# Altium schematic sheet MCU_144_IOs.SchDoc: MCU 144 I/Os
size A3; Date: Not used; ApprovedBy: Not used; CheckedBy: Not used; Author: Not used; CompanyName: STMicroelectronics; DrawnBy: Not used; Engineer: Not used; Organization: Not used; Address1: Not used; Address2: Not used; Address3: Not used; Address4: Not used; DocumentNumber: 3; Revision: Not used; SheetNumber: 3; SheetTotal: 9
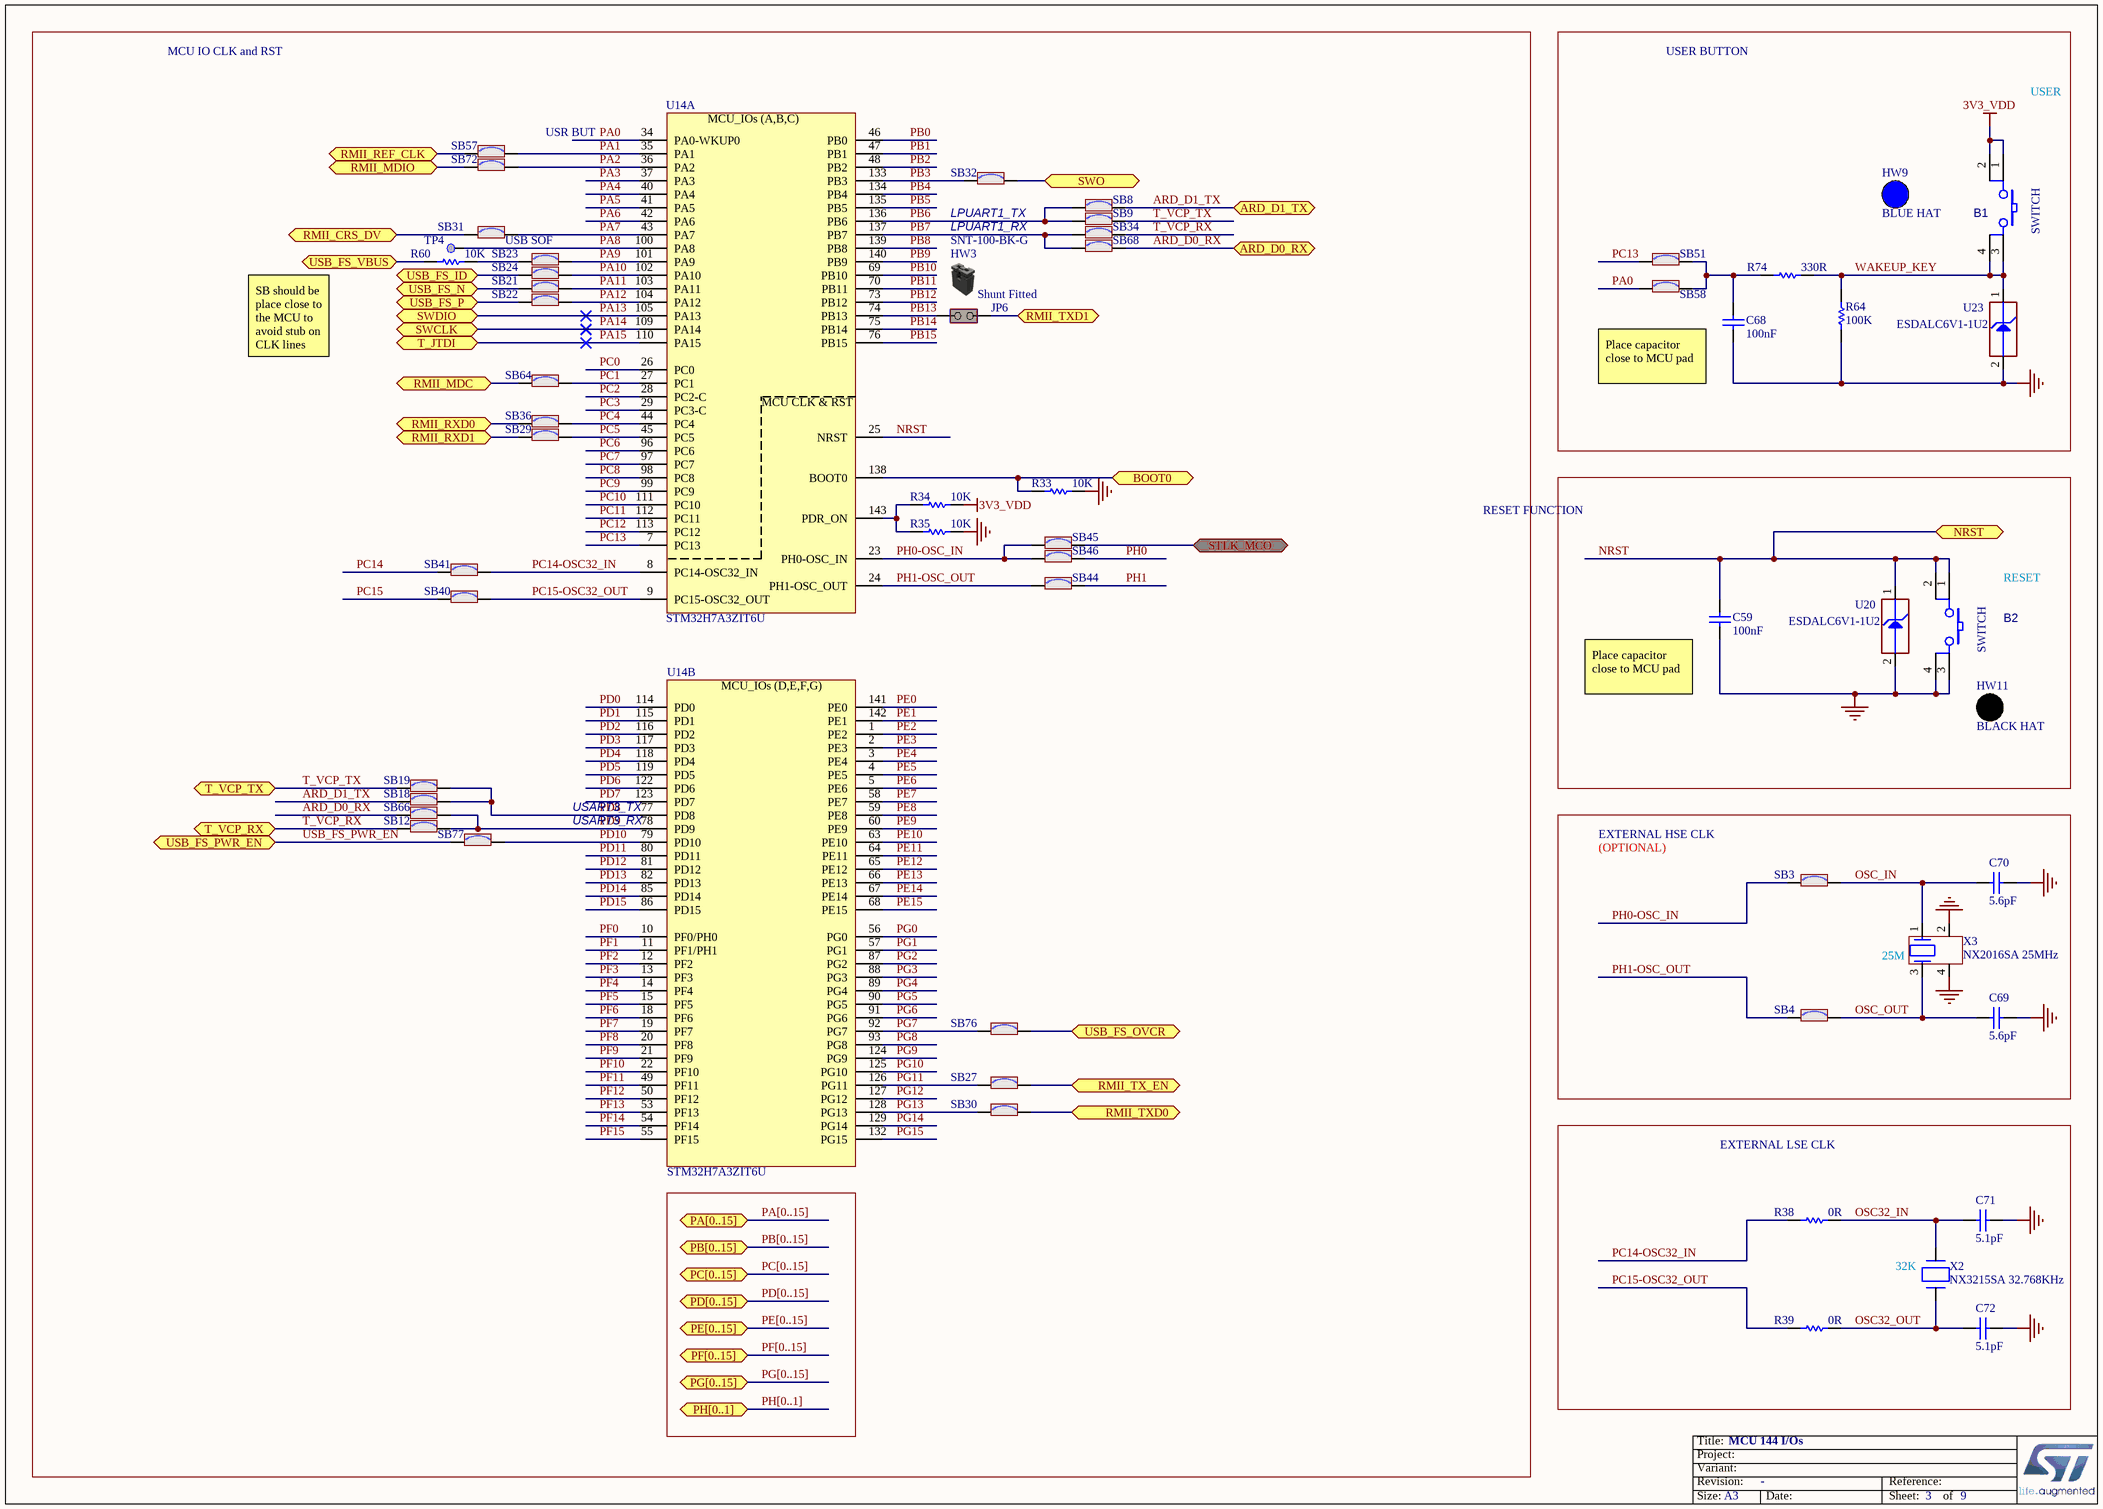
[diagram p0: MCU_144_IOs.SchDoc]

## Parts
B1  value SWITCH  [SWI_WEALTHMETAL_TD-0341_4P_BLUE]  (hidden comment: SW-PUSH-CMS)
B2  value SWITCH  [SWI_WEALTHMETAL_TD-0341_4P_BLACK]  (hidden comment: SW-PUSH-CMS)
C59  value 100nF  [C0603]  (hidden comment: Capacitor)
C68  value 100nF  [C0603]  (hidden comment: Capacitor)
C69  value 5.6pF  [C0402]  (hidden comment: Capacitor)
C70  value 5.6pF  [C0402]  (hidden comment: Capacitor)
C71  value 5.1pF  [C0402]  (hidden comment: Capacitor)
C72  value 5.1pF  [C0402]  (hidden comment: Capacitor)
HW3  value SNT-100-BK-G  (hidden comment: Shunt Black 2.54mm)  (mechanical)
HW9  value BLUE HAT  (hidden comment: BUTTON_HAT_BLUE)  (mechanical)
HW11  value BLACK HAT  (hidden comment: BUTTON_HAT_BLACK)  (mechanical)
JP6  value Shunt Fitted  [CON_SAMTEC_TSW-102-07-G-S]  (hidden comment: Jumper_Header 2x1 Fitted)
R33  value 10K  [R0603]  (hidden comment: Resistor)
R34  value 10K  [R0603]  (hidden comment: Resistor)
R35  value 10K  [R0603]  (hidden comment: Resistor)
R38  value 0R  [R0603]  (hidden comment: Resistor)
R39  value 0R  [R0603]  (hidden comment: Resistor)
R60  value 10K  [R0402]  (hidden comment: Resistor)
R64  value 100K  [R0603]  (hidden comment: Resistor)
R74  value 330R  [R0603]  (hidden comment: Resistor)
SB3  SB_ON  [SOLDER-BRIDGE_R0603-0R]  (value not drawn)
SB4  SB_ON  [SOLDER-BRIDGE_R0603-0R]  (value not drawn)
SB8  SB_ON  [SOLDER-BRIDGE_R0603-0R]  (value not drawn)
SB9  SB_ON  [SOLDER-BRIDGE_R0603-0R]  (value not drawn)
SB12  SB_ON  [SOLDER-BRIDGE_R0603-0R]  (value not drawn)
SB18  SB_ON  [SOLDER-BRIDGE_R0603-0R]  (value not drawn)
SB19  SB_ON  [SOLDER-BRIDGE_R0603-0R]  (value not drawn)
SB21  SB_ON  [SOLDER-BRIDGE_R0603-0R]  (value not drawn)
SB22  SB_ON  [SOLDER-BRIDGE_R0603-0R]  (value not drawn)
SB23  SB_ON  [SOLDER-BRIDGE_R0603-0R]  (value not drawn)
SB24  SB_ON  [SOLDER-BRIDGE_R0603-0R]  (value not drawn)
SB27  SB_ON  [SOLDER-BRIDGE_R0603-0R]  (value not drawn)
SB29  SB_ON  [SOLDER-BRIDGE_R0603-0R]  (value not drawn)
SB30  SB_ON  [SOLDER-BRIDGE_R0603-0R]  (value not drawn)
SB31  SB_ON  [SOLDER-BRIDGE_R0603-0R]  (value not drawn)
SB32  SB_ON  [SOLDER-BRIDGE_R0603-0R]  (value not drawn)
SB34  SB_ON  [SOLDER-BRIDGE_R0603-0R]  (value not drawn)
SB36  SB_ON  [SOLDER-BRIDGE_R0603-0R]  (value not drawn)
SB40  SB_ON  [SOLDER-BRIDGE_R0603-0R]  (value not drawn)
SB41  SB_ON  [SOLDER-BRIDGE_R0603-0R]  (value not drawn)
SB44  SB_ON  [SOLDER-BRIDGE_R0603-0R]  (value not drawn)
SB45  SB_ON  [SOLDER-BRIDGE_R0603-0R]  (value not drawn)
SB46  SB_ON  [SOLDER-BRIDGE_R0603-0R]  (value not drawn)
SB51  SB_ON  [SOLDER-BRIDGE_R0603-0R]  (value not drawn)
SB57  SB_ON  [SOLDER-BRIDGE_R0603-0R]  (value not drawn)
SB58  SB_ON  [SOLDER-BRIDGE_R0603-0R]  (value not drawn)
SB64  SB_ON  [SOLDER-BRIDGE_R0603-0R]  (value not drawn)
SB66  SB_ON  [SOLDER-BRIDGE_R0402-0R]  (value not drawn)
SB68  SB_ON  [SOLDER-BRIDGE_R0402-0R]  (value not drawn)
SB72  SB_ON  [SOLDER-BRIDGE_R0603-0R]  (value not drawn)
SB76  SB_ON  [SOLDER-BRIDGE_R0603-0R]  (value not drawn)
SB77  SB_ON  [SOLDER-BRIDGE_R0603-0R]  (value not drawn)
TP4  Test Point  [TP_SMD_1MM]  (value not drawn)  (no BOM)
U14  value STM32H7A3ZIT6U  [ICC_LQFP144_20X20_P050_SOCKET_YAMAICHI_IC149-144-145-B5_NM]  (hidden comment: STM32H7A3ZIT6)  (parts A,B of 3)
U20  value ESDALC6V1-1U2  [ESD_ST0201]  (hidden comment: ESD-TRANSIL)
U23  value ESDALC6V1-1U2  [ESD_ST0201]  (hidden comment: ESD-TRANSIL)
X2  value NX3215SA 32.768KHz  [CRY_NX3215SA_2P]  (hidden comment: XTAL_2_PINS)
X3  value NX2016SA 25MHz  [CRY_NX2016SA_4P]  (hidden comment: XTAL_4_PINS)

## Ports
ARD_D0_RX (bidir), ARD_D1_TX (bidir), BOOT0 (bidir), NRST (bidir), PA[0..15] (bidir), PB[0..15] (bidir), PC[0..15] (bidir), PD[0..15] (bidir), PE[0..15] (bidir), PF[0..15] (bidir), PG[0..15] (bidir), PH[0..1] (bidir), RMII_CRS_DV (bidir), RMII_MDC (bidir), RMII_MDIO (bidir), RMII_REF_CLK (bidir), RMII_RXD0 (bidir), RMII_RXD1 (bidir), RMII_TX_EN (bidir), RMII_TXD0 (bidir), RMII_TXD1 (bidir), STLK_MCO (bidir), SWCLK (bidir), SWDIO (bidir), SWO (bidir), T_JTDI (bidir), T_VCP_RX (bidir), T_VCP_TX (bidir), USB_FS_ID (bidir), USB_FS_N (bidir), USB_FS_OVCR, USB_FS_P (bidir), USB_FS_PWR_EN (bidir), USB_FS_VBUS (bidir)

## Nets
3V3_VDD: B1.1 B1.2 R34.2
GND: B2.3 B2.4 C59.1 C68.1 C69.2 C70.2 C71.2 C72.2 R33.2 R35.2 R64.1 U20.2(GND) U23.2(GND) X3.2 X3.4
ARD_D0_RX: SB66.1 SB68.2 ; port ARD_D0_RX
ARD_D1_TX: SB8.1 SB18.2 ; port ARD_D1_TX
BOOT0: R33.1 U14.138(BOOT0) ; port BOOT0
NRST: B2.1 B2.2 C59.2 U14.25(NRST) U20.1(IO1) ; port NRST
OSC32_IN: C71.1 R38.2 X2.2(X2)
OSC32_OUT: C72.1 R39.2 X2.1(X1)
OSC_IN: C70.1 SB3.2 X3.1
OSC_OUT: C69.1 SB4.2 X3.3
PA0: SB58.2 U14.34(PA0-WKUP0)
PA1: SB57.1 U14.35(PA1)
PA2: SB72.1 U14.36(PA2)
PA3: U14.37(PA3)
PA4: U14.40(PA4)
PA5: U14.41(PA5)
PA6: U14.42(PA6)
PA7: SB31.1 U14.43(PA7)
PA8: TP4.1 U14.100(PA8)
PA9: SB23.1 U14.101(PA9)
PA10: SB24.1 U14.102(PA10)
PA11: SB21.1 U14.103(PA11)
PA12: SB22.1 U14.104(PA12)
PA13: U14.105(PA13) ; port SWDIO
PA14: U14.109(PA14) ; port SWCLK
PA15: U14.110(PA15) ; port T_JTDI
PB0: U14.46(PB0)
PB1: U14.47(PB1)
PB2: U14.48(PB2)
PB3: SB32.2 U14.133(PB3)
PB4: U14.134(PB4)
PB5: U14.135(PB5)
PB6: SB8.2 SB9.2 U14.136(PB6)
PB7: SB34.2 SB68.1 U14.137(PB7)
PB8: U14.139(PB8)
PB9: U14.140(PB9)
PB10: U14.69(PB10)
PB11: U14.70(PB11)
PB12: U14.73(PB12)
PB13: JP6.1(COMMON) U14.74(PB13)
PB14: U14.75(PB14)
PB15: U14.76(PB15)
PC0: U14.26(PC0)
PC1: SB64.2 U14.27(PC1)
PC2: U14.28(PC2-C)
PC3: U14.29(PC3-C)
PC4: SB36.2 U14.44(PC4)
PC5: SB29.2 U14.45(PC5)
PC6: U14.96(PC6)
PC7: U14.97(PC7)
PC8: U14.98(PC8)
PC9: U14.99(PC9)
PC10: U14.111(PC10)
PC11: U14.112(PC11)
PC12: U14.113(PC12)
PC13: SB51.2 U14.7(PC13)
PC14: SB41.1
PC14-OSC32_IN: R38.1 SB41.2 U14.8(PC14-OSC32_IN)
PC15: SB40.1
PC15-OSC32_OUT: R39.1 SB40.2 U14.9(PC15-OSC32_OUT)
PD0: U14.114(PD0)
PD1: U14.115(PD1)
PD2: U14.116(PD2)
PD3: U14.117(PD3)
PD4: U14.118(PD4)
PD5: U14.119(PD5)
PD6: U14.122(PD6)
PD7: U14.123(PD7)
PD8: SB18.1 SB19.1 U14.77(PD8)
PD9: SB12.1 SB66.2 U14.78(PD9)
PD10: SB77.1 U14.79(PD10)
PD11: U14.80(PD11)
PD12: U14.81(PD12)
PD13: U14.82(PD13)
PD14: U14.85(PD14)
PD15: U14.86(PD15)
PE0: U14.141(PE0)
PE1: U14.142(PE1)
PE2: U14.1(PE2)
PE3: U14.2(PE3)
PE4: U14.3(PE4)
PE5: U14.4(PE5)
PE6: U14.5(PE6)
PE7: U14.58(PE7)
PE8: U14.59(PE8)
PE9: U14.60(PE9)
PE10: U14.63(PE10)
PE11: U14.64(PE11)
PE12: U14.65(PE12)
PE13: U14.66(PE13)
PE14: U14.67(PE14)
PE15: U14.68(PE15)
PF0: U14.10(PF0/PH0)
PF1: U14.11(PF1/PH1)
PF2: U14.12(PF2)
PF3: U14.13(PF3)
PF4: U14.14(PF4)
PF5: U14.15(PF5)
PF6: U14.18(PF6)
PF7: U14.19(PF7)
PF8: U14.20(PF8)
PF9: U14.21(PF9)
PF10: U14.22(PF10)
PF11: U14.49(PF11)
PF12: U14.50(PF12)
PF13: U14.53(PF13)
PF14: U14.54(PF14)
PF15: U14.55(PF15)
PG0: U14.56(PG0)
PG1: U14.57(PG1)
PG2: U14.87(PG2)
PG3: U14.88(PG3)
PG4: U14.89(PG4)
PG5: U14.90(PG5)
PG6: U14.91(PG6)
PG7: SB76.2 U14.92(PG7)
PG8: U14.93(PG8)
PG9: U14.124(PG9)
PG10: U14.125(PG10)
PG11: SB27.2 U14.126(PG11)
PG12: U14.127(PG12)
PG13: SB30.2 U14.128(PG13)
PG14: U14.129(PG14)
PG15: U14.132(PG15)
PH0: SB46.2
PH0-OSC_IN: SB3.1 SB45.1 SB46.1 U14.23(PH0-OSC_IN)
PH1: SB44.2
PH1-OSC_OUT: SB4.1 SB44.1 U14.24(PH1-OSC_OUT)
RMII_CRS_DV: SB31.2 ; port RMII_CRS_DV
RMII_MDC: SB64.1 ; port RMII_MDC
RMII_MDIO: SB72.2 ; port RMII_MDIO
RMII_REF_CLK: SB57.2 ; port RMII_REF_CLK
RMII_RXD0: SB36.1 ; port RMII_RXD0
RMII_RXD1: SB29.1 ; port RMII_RXD1
RMII_TX_EN: SB27.1 ; port RMII_TX_EN
RMII_TXD0: SB30.1 ; port RMII_TXD0
RMII_TXD1: JP6.2(NO) ; port RMII_TXD1
STLK_MCO: SB45.2 ; port STLK_MCO
SWO: SB32.1 ; port SWO
T_VCP_RX: SB12.2 SB34.1 ; port T_VCP_RX
T_VCP_TX: SB9.1 SB19.2 ; port T_VCP_TX
USB_FS_ID: SB24.2 ; port USB_FS_ID
USB_FS_N: SB21.2 ; port USB_FS_N
USB_FS_OVCR: SB76.1 ; port USB_FS_OVCR
USB_FS_P: SB22.2 ; port USB_FS_P
USB_FS_PWR_EN: SB77.2 ; port USB_FS_PWR_EN
USB_FS_VBUS: R60.1 ; port USB_FS_VBUS
WAKEUP_KEY: B1.3 B1.4 R64.2 R74.2 U23.1(IO1)
NetC68_2: C68.2 R74.1 SB51.1 SB58.1
NetR34_1: R34.1 R35.1 U14.143(PDR_ON)
NetR60_2: R60.2 SB23.2

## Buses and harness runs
bus PA[0..15] = port PA[0..15]
bus PB[0..15] = port PB[0..15]
bus PC[0..15] = port PC[0..15]
bus PD[0..15] = port PD[0..15]
bus PE[0..15] = port PE[0..15]
bus PF[0..15] = port PF[0..15]
bus PG[0..15] = port PG[0..15]
bus PH[0..1] = port PH[0..1]

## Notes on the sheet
- MCU IO CLK and RST
- USER BUTTON
- USER
- USR BUT
- (near SB31) USB SOF
- LPUART1_TX
- LPUART1_RX
- SB should be place close to the MCU to avoid stub on CLK lines
- Place capacitor close to MCU pad
- RESET FUNCTION
- RESET
- (near C59) Place capacitor close to MCU pad
- (near SB77) USART3_TX
- (near SB77) USART3_RX
- EXTERNAL HSE CLK
- (OPTIONAL)
- (near X3) 25M
- EXTERNAL LSE CLK
- (near X2) 32K

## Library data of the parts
B1 = MCD-00002: Non-Open Push-Button 0.1A 24V; Manufacturer_Part_Number: TD-0341; Manufacturer: WEALTHMETAL; Part_Type: Misc; Provided_By: SUBCO
B2 = MCD-00001: Non-Open Push-Button 0.1A 24V BLACK; Manufacturer_Part_Number: TD-0341; Manufacturer: WEALTHMETAL; Part_Type: Misc; Provided_By: SUBCO
C59 C68 = MCD-00237: Capacitor, MLCC, 100nF, 6V3, X5R, 10%, 0603, T=0,8mm; Manufacturer_Part_Number: CC0603KRX5R5BB104; Manufacturer: YAGEO; Provided_By: SUBCO; ECCN_US: EAR99; ECCN_EU: NEC
C69 C70 = MCD-01374: Capacitor, MLCC, 5.6pF, 50V, NPO, 5%, 0402, T=0,5mm; Manufacturer_Part_Number: CC0402BRNPO9BN5R6; Manufacturer: YAGEO; Provided_By: SUBCO
C71 C72 = MCD-00003: Capacitor, MLCC, 5.1pF, 50V, NPO, +-0.25pF, 0402, T=0.5mm; Manufacturer_Part_Number: CC0402CRNPO9BN5R1; Manufacturer: YAGEO; Provided_By: SUBCO; ECCN_US: EAR99; ECCN_EU: NEC
HW3 = MCD-00043: SHUNT 2.54mm BLACK; Manufacturer: SAMTEC; Part_Type: Mechanical; Alternate_Manufacturer_Part_Number: 316102S111A; Alternate_Manufacturer: JIUBABA; Provided_By: SUBCO
HW9 = MCD-00634: Blue Hat for switch TD0341X-G01-BLU; Part_Type: Mechanical; Manufacturer_Part_Number: 988.16.09.3.00002_SH-517; Manufacturer: JIUBABA; Provided_By: SUBCO
HW11 = MCD-00635: Black Hat for switch TD0341X-G01-BLA; Part_Type: Mechanical; Manufacturer_Part_Number: 988.16.09.3.00003_SH-517; Manufacturer: JIUBABA; Provided_By: SUBCO
JP6 = MCD-00683: Header, 2x1, 2,54mm, VR, TH, Height 5.84mm/2.54mm - Shunt Fitted by default; Part_Type: Connector; Manufacturer_Part_Number: TSW-102-07-x-S; Manufacturer: SAMTEC; Alternate_Manufacturer_Part_Number: 313102S111116; Alternate_Manufacturer: LIANYI; Provided_By: SUBCO
R33-R35 = MCD-00220: Resistor,10K,0603,1%,1/10W; Manufacturer_Part_Number: RC0603FR-0710KL; Manufacturer: YAGEO; Provided_By: SUBCO; ECCN_US: EAR99; ECCN_EU: NEC
R38 R39 = MCD-00056: Resistor,0R,0603,5%,1/10W; Manufacturer_Part_Number: RC0603JR-070RL; Manufacturer: YAGEO; Provided_By: SUBCO; ECCN_US: EAR99; ECCN_EU: NEC
R60 = MCD-00053: Resistor,10K,0402,1%,1/16W; Manufacturer_Part_Number: RC0402FR-0710KL; Manufacturer: YAGEO; Provided_By: SUBCO; ECCN_US: EAR99; ECCN_EU: NEC
R64 = MCD-00223: Resistor,100K,0603,1%,1/10W; Manufacturer_Part_Number: RC0603FR-07100KL; Manufacturer: YAGEO; Provided_By: SUBCO; ECCN_US: EAR99; ECCN_EU: NEC
R74 = MCD-00197: Resistor,330R,0603,1%,1/10W; Manufacturer_Part_Number: RC0603FR-07330RL; Manufacturer: YAGEO; BMS_Part_Number: 9129729; Provided_By: SUBCO; ECCN_US: EAR99; ECCN_EU: NEC
SB3 SB4 SB8 SB9 SB12 SB18 SB19 SB21-SB24 SB27 SB29-SB32 SB34 SB36 SB40 SB41 SB44-SB46 SB51 SB57 SB58 SB64 SB72 SB76 SB77 = MCD-00071: Solder Bridge ON; Part_Type: Mechanical; Manufacturer_Part_Number: RC0603JR-070RL; Manufacturer: YAGEO; Provided_By: SUBCO
SB66 SB68 = MCD-01618: Solder Bridge 0402 ON; Part_Type: Mechanical; Manufacturer_Part_Number: RC0402JR-070RL; Manufacturer: YAGEO; Provided_By: SUBCO
TP4 = MCD-00074: Test Point 1mm; Part_Type: Mechanical
U14 = MCD-01349: STM32H7A3ZIT6U, LQFP144 package, 20x20; Part_Type: IC; Manufacturer: STMICROELECTRONICS; BMS_Part_Number: 9175347; Provided_By: SUBCO with ST control; ECCN_US: 3A991A2; ECCN_EU: NEC
U20 U23 = MCD-00170: ESD protection 6V1; Part_Type: Diode; Manufacturer: STMICROELECTRONICS; BMS_Part_Number: 9151132; Provided_By: SUBCO with ST control; ECCN_US: EAR99; ECCN_EU: NEC
X2 = MCD-00091: Crystal 32.768kHz, 6pF, +-20ppm, 50Kohms max, SMD; Manufacturer_Part_Number: NX3215SA 32.768KHz EXS00A-MU00525; Manufacturer: NDK; Part_Type: Crystal_Osc; BMS_Part_Number: 9157034; Provided_By: SUBCO; ECCN_US: EAR99; ECCN_EU: NEC
X3 = MCD-01364: Crystal 25MHz, 6pF, +-20ppm, 80ohms max, SMD; Part_Type: Crystal_Osc; Manufacturer_Part_Number: NX2016SA 25MHz EXS00A-CS11321; Manufacturer: NDK; BMS_Part_Number: 9157044; Provided_By: SUBCO; ECCN_US: EAR99; ECCN_EU: NEC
